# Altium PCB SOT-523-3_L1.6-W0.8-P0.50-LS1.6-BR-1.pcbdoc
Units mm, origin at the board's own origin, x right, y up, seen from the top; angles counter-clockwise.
Board outline 14.72 x 14.48 mm, 2 copper layers (Top Layer, Bottom Layer), stack 0 mm thick; 1 components, 0 nets, 3 pads, 0 vias.
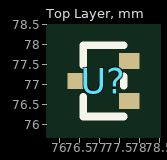
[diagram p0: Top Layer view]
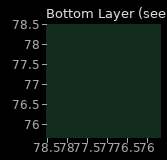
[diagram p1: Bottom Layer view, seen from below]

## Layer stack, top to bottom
Top Layer: signal copper (thickness not stored)
Bottom Layer: signal copper (thickness not stored)

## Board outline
84.566,69.85 69.85,69.85 69.85,84.328 84.566,84.328

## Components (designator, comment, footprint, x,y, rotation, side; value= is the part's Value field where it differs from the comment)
U? "" SOT-523-3_L1.6-W0.8-P0.50-LS1.6-BR-1 77.1,77.089 r0 top

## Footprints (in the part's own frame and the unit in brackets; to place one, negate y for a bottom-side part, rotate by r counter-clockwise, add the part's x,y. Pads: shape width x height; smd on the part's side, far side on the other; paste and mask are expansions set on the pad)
SOT-523-3_L1.6-W0.8-P0.50-LS1.6-BR-1 [mm]
  rect 0.51x0.4 smd paste+0 mask+0.05: 1(0.645,-0.5) 2(0.645,0.5) 3(-0.645,0)
  silkscreen extent -0.51,-0.89 0.51,0.89

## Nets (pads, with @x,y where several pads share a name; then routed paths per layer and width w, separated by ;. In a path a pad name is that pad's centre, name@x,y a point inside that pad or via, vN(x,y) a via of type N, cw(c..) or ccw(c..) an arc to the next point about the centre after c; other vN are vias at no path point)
pads on no net: U?.1 U?.2 U?.3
